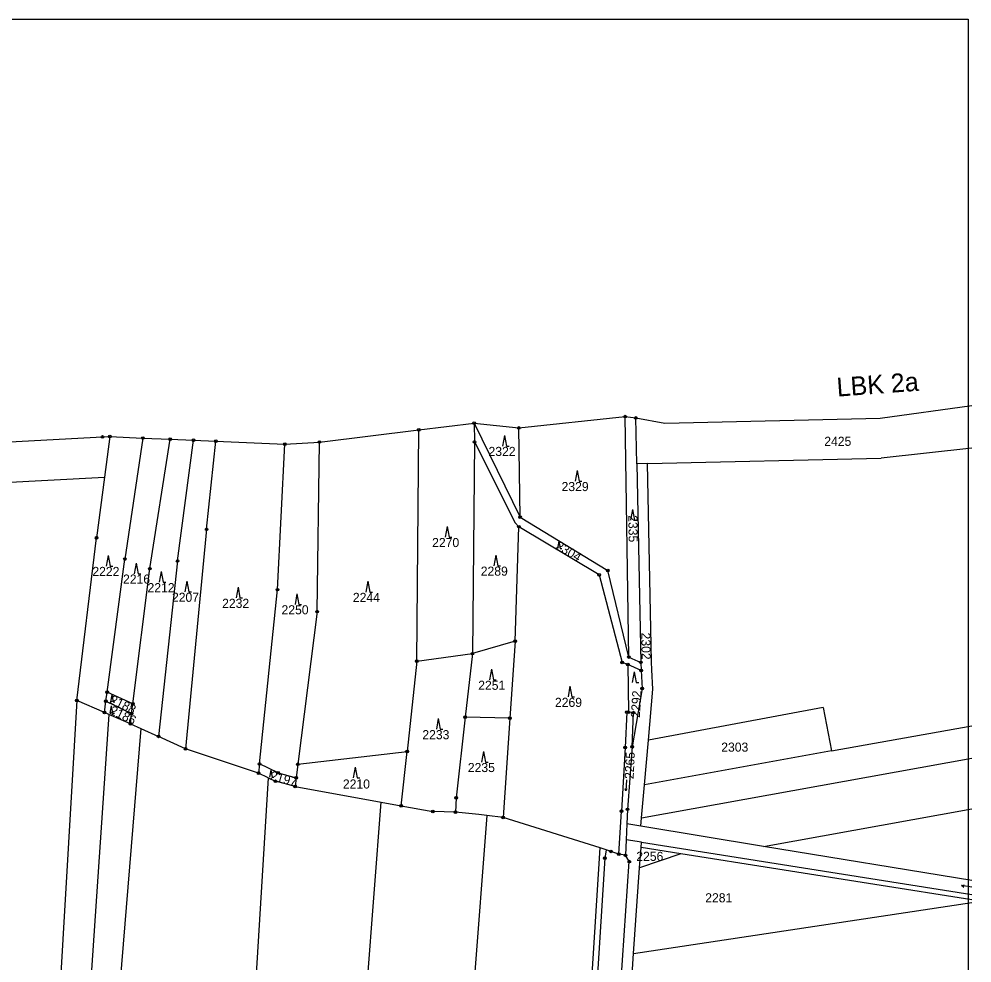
# Model space of a CAD drawing. Extents: x -566461 to -565197, y -1096302 to -1095706.
# Drawn here: x -565553.3 to -565197, y -1096059.8 to -1095707 of the extents above; entities that cross this region are included whole.
import ezdxf

# ---------------------------------------------------------------- set-up
doc = ezdxf.new("R2010")
doc.units = 0
for name, color, linetype in [('Vrstva 1', 7, 'Continuous'), ('Vrstva 13', 7, 'Continuous'), ('Vrstva 18', 7, 'Continuous'), ('Vrstva 24', 7, 'Continuous'), ('Vrstva 25', 7, 'Continuous'), ('Vrstva 63', 7, 'Continuous')]:
    doc.layers.add(name, color=color, linetype=linetype)

msp = doc.modelspace()

# ---------------------------------------------------------------- linework, layer by layer
at = {"layer": 'Vrstva 1'}
for p, q in [((-565325.3, -1095945.49), (-565326.62, -1095855.64)), ((-565322.28, -1095873.28), (-565322.62, -1095856.13)), ((-565404.57, -1095947.01), (-565403.8, -1095860.58)), ((-565383.09, -1095858.05), (-565383.02, -1095865.11)), ((-565383.09, -1095858.05), (-565365.95, -1095893.19)), ((-565365.95, -1095893.19), (-565366.41, -1095859.87)), ((-565519.36, -1095863.08), (-565521.32, -1095878.21)), ((-565506.96, -1095863.62), (-565513.66, -1095908.86)), ((-565504.35, -1095912.44), (-565496.71, -1095864.05)), ((-565493.97, -1095909.58), (-565488.06, -1095864.42)), ((-565483.13, -1095897.74), (-565479.68, -1095864.78)), ((-565456.67, -1095920.29), (-565453.87, -1095865.89)), ((-565441.83, -1095928.52), (-565440.98, -1095865.12)), ((-565383.02, -1095865.11), (-565383.78, -1095944.21)), ((-565383.02, -1095865.11), (-565367.82, -1095895.28)), ((-565196.99, -1095867.39), (-565230.93, -1095871.19)), ((-565318.28, -1095873.19), (-565230.93, -1095871.19)), ((-565318.28, -1095873.19), (-565322.28, -1095873.28)), ((-565322.28, -1095873.28), (-565320.79, -1095947.48)), ((-565316.79, -1095947.33), (-565318.28, -1095873.19)), ((-565568.01, -1095880.69), (-565521.32, -1095878.21)), ((-565521.32, -1095878.21), (-565524.26, -1095900.94)), ((-565366.39, -1095896.77), (-565367.82, -1095895.28)), ((-565365.95, -1095893.19), (-565333.17, -1095913.11)), ((-565483.13, -1095897.74), (-565490.98, -1095979.78)), ((-565367.79, -1095939.56), (-565366.39, -1095896.77)), ((-565336.37, -1095914.75), (-565366.39, -1095896.77)), ((-565531.63, -1095961.73), (-565524.26, -1095900.94)), ((-565520.34, -1095958.64), (-565513.66, -1095908.86)), ((-565493.97, -1095909.58), (-565501.17, -1095975.14)), ((-565510.71, -1095963.01), (-565504.35, -1095912.44)), ((-565325.3, -1095945.49), (-565333.17, -1095913.11)), ((-565336.37, -1095914.75), (-565327.73, -1095947.49)), ((-565463.34, -1095985.45), (-565456.67, -1095920.29)), ((-565441.83, -1095928.52), (-565449.03, -1095985.59)), ((-565367.79, -1095939.56), (-565383.78, -1095944.21)), ((-565367.79, -1095939.56), (-565369.72, -1095968.34)), ((-565404.57, -1095947.01), (-565383.78, -1095944.21)), ((-565383.78, -1095944.21), (-565386.46, -1095967.93)), ((-565325.3, -1095945.49), (-565320.79, -1095947.48)), ((-565404.57, -1095947.01), (-565408.18, -1095980.8)), ((-565325.61, -1095948.29), (-565327.73, -1095947.49)), ((-565325.61, -1095948.29), (-565325.42, -1095966.15)), ((-565320.63, -1095950.54), (-565325.61, -1095948.29)), ((-565320.79, -1095947.48), (-565320.63, -1095950.54)), ((-565316.63, -1095950.33), (-565316.79, -1095947.33)), ((-565320.63, -1095950.54), (-565320.28, -1095957.29)), ((-565316.26, -1095957.53), (-565316.63, -1095950.33)), ((-565520.79, -1095961.97), (-565520.34, -1095958.64)), ((-565510.71, -1095963.01), (-565520.34, -1095958.64)), ((-565320.28, -1095957.29), (-565324.05, -1095979.07)), ((-565317.95, -1095976.6), (-565316.26, -1095957.53)), ((-565531.63, -1095961.73), (-565540.94, -1096119.67)), ((-565521.36, -1095966.2), (-565531.63, -1095961.73)), ((-565521.36, -1095966.2), (-565520.79, -1095961.97)), ((-565520.79, -1095961.97), (-565511.17, -1095966.63)), ((-565511.17, -1095966.63), (-565510.71, -1095963.01)), ((-565519.73, -1095966.91), (-565530.09, -1096119.67)), ((-565519.73, -1095966.91), (-565521.36, -1095966.2)), ((-565511.64, -1095970.44), (-565519.73, -1095966.91)), ((-565511.64, -1095970.44), (-565511.17, -1095966.63)), ((-565326.08, -1095966.11), (-565326.66, -1095979.34)), ((-565326.08, -1095966.11), (-565325.42, -1095966.15)), ((-565323.47, -1095966.28), (-565325.42, -1095966.15)), ((-565324.05, -1095979.07), (-565323.47, -1095966.28)), ((-565252.64, -1095964.38), (-565317.95, -1095976.6)), ((-565252.64, -1095964.38), (-565249.5, -1095980.6)), ((-565511.64, -1095970.44), (-565507.79, -1095972.17)), ((-565386.46, -1095967.93), (-565389.86, -1095998.08)), ((-565369.72, -1095968.34), (-565386.46, -1095967.93)), ((-565369.72, -1095968.34), (-565372.21, -1096005.43)), ((-565249.5, -1095980.6), (-565196.99, -1095971.15)), ((-565507.79, -1095972.17), (-565519.76, -1096119.67)), ((-565507.79, -1095972.17), (-565501.17, -1095975.14)), ((-565490.98, -1095979.78), (-565501.17, -1095975.14)), ((-565319.41, -1095993.25), (-565317.95, -1095976.6)), ((-565463.69, -1095988.88), (-565490.98, -1095979.78)), ((-565449.03, -1095985.59), (-565408.18, -1095980.8)), ((-565410.35, -1096001.11), (-565408.18, -1095980.8)), ((-565326.66, -1095979.34), (-565328.04, -1096003.07)), ((-565324.05, -1095979.07), (-565325.74, -1096002.43)), ((-565249.5, -1095980.6), (-565319.41, -1095993.25)), ((-565463.34, -1095985.45), (-565463.69, -1095988.88)), ((-565456.43, -1095988.79), (-565463.34, -1095985.45)), ((-565449.03, -1095985.59), (-565449.67, -1095990.68)), ((-565320.5, -1096005.65), (-565196.99, -1095983.35)), ((-565460.14, -1095990.61), (-565463.69, -1095988.88)), ((-565456.43, -1095988.79), (-565449.67, -1095990.68)), ((-565460.14, -1095990.61), (-565466.93, -1096101.52)), ((-565460.14, -1095990.61), (-565457.43, -1095991.93)), ((-565450.08, -1095993.9), (-565457.43, -1095991.93)), ((-565449.67, -1095990.68), (-565450.08, -1095993.9)), ((-565450.08, -1095993.9), (-565417.9, -1095999.74)), ((-565320.5, -1096005.65), (-565319.41, -1095993.25)), ((-565427.07, -1096119.67), (-565417.9, -1095999.74)), ((-565417.9, -1095999.74), (-565410.35, -1096001.11)), ((-565389.86, -1095998.08), (-565390.13, -1096003.44)), ((-565410.35, -1096001.11), (-565398.57, -1096003.25)), ((-565390.13, -1096003.44), (-565398.57, -1096003.25)), ((-565329.05, -1096019.13), (-565328.04, -1096003.07)), ((-565325.74, -1096002.43), (-565325.98, -1096007.86)), ((-565274.95, -1096016.25), (-565196.99, -1096002.17)), ((-565381.38, -1096004.3), (-565390.13, -1096003.44)), ((-565378.38, -1096004.67), (-565387.09, -1096119.67)), ((-565378.38, -1096004.67), (-565381.38, -1096004.3)), ((-565372.21, -1096005.43), (-565378.38, -1096004.67)), ((-565336.02, -1096016.85), (-565372.21, -1096005.43)), ((-565320.77, -1096008.72), (-565320.5, -1096005.65)), ((-565325.98, -1096007.86), (-565326.25, -1096013.79)), ((-565320.77, -1096008.72), (-565325.98, -1096007.86)), ((-565274.95, -1096016.25), (-565320.77, -1096008.72)), ((-565326.25, -1096013.79), (-565326.51, -1096019.6)), ((-565320.57, -1096014.69), (-565326.25, -1096013.79)), ((-565342.55, -1096119.67), (-565336.02, -1096016.85)), ((-565333.74, -1096017.57), (-565336.02, -1096016.85)), ((-565333.74, -1096017.57), (-565334.25, -1096020.7)), ((-565332, -1096018.12), (-565333.74, -1096017.57)), ((-565321.24, -1096024.26), (-565320.71, -1096016.69)), ((-565320.71, -1096016.69), (-565320.57, -1096014.69)), ((-565305.78, -1096019.05), (-565320.71, -1096016.69)), ((-565320.57, -1096014.69), (-565196.99, -1096034.23)), ((-565196.99, -1096029.05), (-565274.95, -1096016.25)), ((-565334.25, -1096020.7), (-565340.54, -1096119.67)), ((-565329.05, -1096019.13), (-565332, -1096018.12)), ((-565326.51, -1096019.6), (-565329.05, -1096019.13)), ((-565325.09, -1096021.97), (-565326.51, -1096019.6)), ((-565305.78, -1096019.05), (-565321.24, -1096024.26)), ((-565196.99, -1096036.24), (-565305.78, -1096019.05)), ((-565331.88, -1096119.67), (-565325.09, -1096021.97)), ((-565323.47, -1096056.29), (-565321.24, -1096024.26)), ((-565323.47, -1096056.29), (-565196.99, -1096037.21)), ((-565326.92, -1096105.96), (-565323.47, -1096056.29))]:
    msp.add_line(p, q, dxfattribs=at)
at = {"layer": 'Vrstva 13'}
for p, q in [((-565231.27, -1095856.19), (-565196.99, -1095851.52)), ((-565366.41, -1095859.87), (-565326.62, -1095855.64)), ((-565326.62, -1095855.64), (-565322.62, -1095856.13)), ((-565322.62, -1095856.13), (-565311.82, -1095858.04)), ((-565311.82, -1095858.04), (-565231.27, -1095856.19)), ((-565440.98, -1095865.12), (-565403.8, -1095860.58)), ((-565403.8, -1095860.58), (-565383.09, -1095858.05)), ((-565383.09, -1095858.05), (-565366.41, -1095859.87)), ((-565569.62, -1095865.76), (-565522.03, -1095863.23)), ((-565522.03, -1095863.23), (-565519.36, -1095863.08)), ((-565519.36, -1095863.08), (-565506.96, -1095863.62)), ((-565506.96, -1095863.62), (-565496.71, -1095864.05)), ((-565496.71, -1095864.05), (-565488.06, -1095864.42)), ((-565488.06, -1095864.42), (-565479.68, -1095864.78)), ((-565479.68, -1095864.78), (-565453.87, -1095865.89)), ((-565453.87, -1095865.89), (-565440.98, -1095865.12))]:
    msp.add_line(p, q, dxfattribs=at)
at = {"layer": 'Vrstva 24'}
for centre, radius in [((-565326.62, -1095855.64), 0.5), ((-565326.62, -1095855.64), 0.0327), ((-565322.62, -1095856.13), 0.5), ((-565322.62, -1095856.13), 0.0327), ((-565403.8, -1095860.58), 0.5), ((-565403.8, -1095860.58), 0.0327), ((-565383.09, -1095858.05), 0.5), ((-565383.09, -1095858.05), 0.0327), ((-565366.41, -1095859.87), 0.5), ((-565366.41, -1095859.87), 0.0327), ((-565522.03, -1095863.23), 0.5), ((-565522.03, -1095863.23), 0.0327), ((-565519.36, -1095863.08), 0.5), ((-565519.36, -1095863.08), 0.0327), ((-565506.96, -1095863.62), 0.5), ((-565506.96, -1095863.62), 0.0327), ((-565496.71, -1095864.05), 0.5), ((-565496.71, -1095864.05), 0.0327), ((-565488.06, -1095864.42), 0.5), ((-565488.06, -1095864.42), 0.0327), ((-565479.68, -1095864.78), 0.5), ((-565479.68, -1095864.78), 0.0327), ((-565453.87, -1095865.89), 0.5), ((-565453.87, -1095865.89), 0.0327), ((-565440.98, -1095865.12), 0.5), ((-565440.98, -1095865.12), 0.0327), ((-565383.02, -1095865.11), 0.5), ((-565383.02, -1095865.11), 0.0327), ((-565365.95, -1095893.19), 0.5), ((-565366.39, -1095896.77), 0.5), ((-565365.95, -1095893.19), 0.0327), ((-565483.13, -1095897.74), 0.5), ((-565483.13, -1095897.74), 0.0327), ((-565366.39, -1095896.77), 0.0327), ((-565524.26, -1095900.94), 0.5), ((-565524.26, -1095900.94), 0.0327), ((-565513.66, -1095908.86), 0.5), ((-565513.66, -1095908.86), 0.0327), ((-565493.97, -1095909.58), 0.5), ((-565493.97, -1095909.58), 0.0327), ((-565504.35, -1095912.44), 0.5), ((-565504.35, -1095912.44), 0.0327), ((-565336.37, -1095914.75), 0.5), ((-565333.17, -1095913.11), 0.5), ((-565333.17, -1095913.11), 0.0327), ((-565336.37, -1095914.75), 0.0327), ((-565456.67, -1095920.29), 0.5), ((-565456.67, -1095920.29), 0.0327), ((-565441.83, -1095928.52), 0.5), ((-565441.83, -1095928.52), 0.0327), ((-565367.79, -1095939.56), 0.5), ((-565367.79, -1095939.56), 0.0327), ((-565383.78, -1095944.21), 0.5), ((-565383.78, -1095944.21), 0.0327), ((-565325.3, -1095945.49), 0.5), ((-565325.3, -1095945.49), 0.0327), ((-565404.57, -1095947.01), 0.5), ((-565404.57, -1095947.01), 0.0327), ((-565327.73, -1095947.49), 0.5), ((-565327.73, -1095947.49), 0.0327), ((-565325.61, -1095948.29), 0.5), ((-565325.61, -1095948.29), 0.0327), ((-565320.79, -1095947.48), 0.5), ((-565320.79, -1095947.48), 0.0327), ((-565320.63, -1095950.54), 0.5), ((-565320.63, -1095950.54), 0.0327), ((-565320.28, -1095957.29), 0.5), ((-565520.34, -1095958.64), 0.5), ((-565520.34, -1095958.64), 0.0327), ((-565320.28, -1095957.29), 0.0327), ((-565531.63, -1095961.73), 0.5), ((-565531.63, -1095961.73), 0.0327), ((-565520.79, -1095961.97), 0.5), ((-565520.79, -1095961.97), 0.0327), ((-565510.71, -1095963.01), 0.5), ((-565510.71, -1095963.01), 0.0327), ((-565521.36, -1095966.2), 0.5), ((-565521.36, -1095966.2), 0.0327), ((-565511.17, -1095966.63), 0.5), ((-565511.17, -1095966.63), 0.0327), ((-565386.46, -1095967.93), 0.5), ((-565326.08, -1095966.11), 0.5), ((-565326.08, -1095966.11), 0.0327), ((-565325.42, -1095966.15), 0.5), ((-565325.42, -1095966.15), 0.0327), ((-565323.47, -1095966.28), 0.5), ((-565323.47, -1095966.28), 0.0327), ((-565511.64, -1095970.44), 0.5), ((-565511.64, -1095970.44), 0.0327), ((-565386.46, -1095967.93), 0.0327), ((-565369.72, -1095968.34), 0.5), ((-565369.72, -1095968.34), 0.0327), ((-565501.17, -1095975.14), 0.5), ((-565501.17, -1095975.14), 0.0327), ((-565490.98, -1095979.78), 0.5), ((-565490.98, -1095979.78), 0.0327), ((-565408.18, -1095980.8), 0.5), ((-565408.18, -1095980.8), 0.0327), ((-565326.66, -1095979.34), 0.5), ((-565326.66, -1095979.34), 0.0327), ((-565324.05, -1095979.07), 0.5), ((-565324.05, -1095979.07), 0.0327), ((-565463.34, -1095985.45), 0.5), ((-565463.34, -1095985.45), 0.0327), ((-565449.03, -1095985.59), 0.5), ((-565449.03, -1095985.59), 0.0327), ((-565463.69, -1095988.88), 0.5), ((-565463.69, -1095988.88), 0.0327), ((-565456.43, -1095988.79), 0.5), ((-565456.43, -1095988.79), 0.0327), ((-565457.43, -1095991.93), 0.5), ((-565457.43, -1095991.93), 0.0327), ((-565449.67, -1095990.68), 0.5), ((-565449.67, -1095990.68), 0.0327), ((-565450.08, -1095993.9), 0.5), ((-565450.08, -1095993.9), 0.0327), ((-565389.86, -1095998.08), 0.5), ((-565389.86, -1095998.08), 0.0327), ((-565410.35, -1096001.11), 0.5), ((-565410.35, -1096001.11), 0.0327), ((-565398.57, -1096003.25), 0.5), ((-565398.57, -1096003.25), 0.0327), ((-565390.13, -1096003.44), 0.5), ((-565390.13, -1096003.44), 0.0327), ((-565328.04, -1096003.07), 0.5), ((-565328.04, -1096003.07), 0.0327), ((-565325.74, -1096002.43), 0.5), ((-565325.74, -1096002.43), 0.0327), ((-565372.21, -1096005.43), 0.5), ((-565372.21, -1096005.43), 0.0327), ((-565332, -1096018.12), 0.5), ((-565334.25, -1096020.7), 0.5), ((-565334.25, -1096020.7), 0.0327), ((-565332, -1096018.12), 0.0327), ((-565329.05, -1096019.13), 0.5), ((-565329.05, -1096019.13), 0.0327), ((-565326.51, -1096019.6), 0.5), ((-565326.51, -1096019.6), 0.0327), ((-565325.09, -1096021.97), 0.5), ((-565325.09, -1096021.97), 0.0327)]:
    msp.add_circle(centre, radius, dxfattribs=at)
at = {"layer": 'Vrstva 25'}
for p, q in [((-565371.79, -1095862.63), (-565372.53, -1095866.63)), ((-565371.79, -1095862.63), (-565371.06, -1095866.63)), ((-565371.06, -1095866.63), (-565370.06, -1095866.63)), ((-565344.62, -1095875.75), (-565345.35, -1095879.75)), ((-565344.62, -1095875.75), (-565343.89, -1095879.75)), ((-565343.89, -1095879.75), (-565342.89, -1095879.75)), ((-565323.9, -1095890.3), (-565324.64, -1095894.3)), ((-565323.9, -1095890.3), (-565323.17, -1095894.3)), ((-565323.17, -1095894.3), (-565322.17, -1095894.3)), ((-565393.23, -1095896.68), (-565393.96, -1095900.68)), ((-565393.23, -1095896.68), (-565392.5, -1095900.68)), ((-565392.5, -1095900.68), (-565391.5, -1095900.68)), ((-565351.45, -1095902.21), (-565351.94, -1095904.89)), ((-565351.45, -1095902.21), (-565350.95, -1095904.89)), ((-565350.95, -1095904.89), (-565350.28, -1095904.89)), ((-565519.94, -1095907.49), (-565520.68, -1095911.49)), ((-565519.94, -1095907.49), (-565519.21, -1095911.49)), ((-565509.47, -1095910.34), (-565510.2, -1095914.34)), ((-565509.47, -1095910.34), (-565508.74, -1095914.34)), ((-565374.96, -1095907.38), (-565375.7, -1095911.38)), ((-565374.96, -1095907.38), (-565374.23, -1095911.38)), ((-565519.21, -1095911.49), (-565518.21, -1095911.49)), ((-565508.74, -1095914.34), (-565507.74, -1095914.34)), ((-565500.16, -1095913.55), (-565500.9, -1095917.55)), ((-565500.16, -1095913.55), (-565499.43, -1095917.55)), ((-565374.23, -1095911.38), (-565373.23, -1095911.38)), ((-565499.43, -1095917.55), (-565498.43, -1095917.55)), ((-565490.5, -1095917.13), (-565491.23, -1095921.13)), ((-565490.5, -1095917.13), (-565489.77, -1095921.13)), ((-565422.83, -1095917.19), (-565423.57, -1095921.19)), ((-565422.83, -1095917.19), (-565422.1, -1095921.19)), ((-565489.77, -1095921.13), (-565488.77, -1095921.13)), ((-565471.4, -1095919.41), (-565472.14, -1095923.41)), ((-565471.4, -1095919.41), (-565470.67, -1095923.41)), ((-565422.1, -1095921.19), (-565421.1, -1095921.19)), ((-565470.67, -1095923.41), (-565469.67, -1095923.41)), ((-565449.36, -1095921.82), (-565450.09, -1095925.82)), ((-565449.36, -1095921.82), (-565448.63, -1095925.82)), ((-565448.63, -1095925.82), (-565447.63, -1095925.82)), ((-565376.57, -1095950.03), (-565377.31, -1095954.03)), ((-565376.57, -1095950.03), (-565375.84, -1095954.03)), ((-565323.27, -1095951), (-565324.01, -1095955)), ((-565323.27, -1095951), (-565322.54, -1095955)), ((-565375.84, -1095954.03), (-565374.84, -1095954.03)), ((-565347.28, -1095956.42), (-565348.02, -1095960.42)), ((-565347.28, -1095956.42), (-565346.55, -1095960.42)), ((-565322.54, -1095955), (-565321.54, -1095955)), ((-565518.62, -1095959.61), (-565519.12, -1095962.29)), ((-565518.62, -1095959.61), (-565518.13, -1095962.29)), ((-565346.55, -1095960.42), (-565345.55, -1095960.42)), ((-565518.78, -1095963.76), (-565519.27, -1095966.44)), ((-565518.78, -1095963.76), (-565518.28, -1095966.44)), ((-565518.13, -1095962.29), (-565517.46, -1095962.29)), ((-565518.28, -1095966.44), (-565517.61, -1095966.44)), ((-565396.51, -1095968.5), (-565397.24, -1095972.5)), ((-565396.51, -1095968.5), (-565395.78, -1095972.5)), ((-565395.78, -1095972.5), (-565394.78, -1095972.5)), ((-565379.58, -1095980.77), (-565380.32, -1095984.77)), ((-565379.58, -1095980.77), (-565378.85, -1095984.77)), ((-565378.85, -1095984.77), (-565377.85, -1095984.77)), ((-565459.18, -1095987.74), (-565459.67, -1095990.42)), ((-565459.18, -1095987.74), (-565458.68, -1095990.42)), ((-565427.58, -1095986.68), (-565428.32, -1095990.68)), ((-565427.58, -1095986.68), (-565426.85, -1095990.68)), ((-565458.68, -1095990.42), (-565458.01, -1095990.42)), ((-565426.85, -1095990.68), (-565425.85, -1095990.68)), ((-565326.2, -1095991.44), (-565326.4, -1095995.46)), ((-565196.99, -1096031.55), (-565200.94, -1096030.92))]:
    msp.add_line(p, q, dxfattribs=at)
for points in [[(-565326.03, -1095994.8), (-565326.4, -1095995.46), (-565326.7, -1095994.77)], [(-565200.03, -1096031.57), (-565200.94, -1096030.92), (-565199.88, -1096030.58)]]:
    msp.add_lwpolyline(points, dxfattribs=at)
at = {"layer": 'Vrstva 63'}
for p, q in [((-566458.38, -1095707.03), (-565198.38, -1095707.03)), ((-565198.38, -1095707.03), (-565198.38, -1096301.03))]:
    msp.add_line(p, q, dxfattribs=at)

# ---------------------------------------------------------------- texts
at = {"layer": 'Vrstva 1'}
msp.add_text('LBK 2a', height=7, rotation=4.1596, dxfattribs=at).set_placement((-565247.32, -1095848.16))
at = {"layer": 'Vrstva 18'}
for s, p in [('2425', (-565252.2, -1095866.55)), ('2322', (-565377.73, -1095870.34)), ('2329', (-565350.42, -1095883.46)), ('2270', (-565398.82, -1095904.39)), ('2222', (-565525.86, -1095915.2)), ('2289', (-565380.64, -1095915.09)), ('2216', (-565514.4, -1095918.05)), ('2212', (-565505.23, -1095921.26)), ('2207', (-565496.09, -1095924.84)), ('2244', (-565428.45, -1095924.9)), ('2232', (-565477.34, -1095927.12)), ('2250', (-565455.13, -1095929.53)), ('2251', (-565381.59, -1095957.74)), ('2269', (-565352.9, -1095964.13)), ('2233', (-565402.48, -1095976.21)), ('2303', (-565290.72, -1095980.87)), ('2235', (-565385.47, -1095988.48)), ('2210', (-565432.18, -1095994.64)), ('2256', (-565322.49, -1096021.69)), ('2281', (-565296.71, -1096037.18))]:
    msp.add_text(s, height=3.4, dxfattribs=at).set_placement(p)
for s, rotation, p in [('2335', 270.9, (-565325.48, -1095892.49)), ('2304', 329.4, (-565353.01, -1095904.85)), ('2302', 270.9, (-565320.63, -1095936.38)), ('2188', 333.9, (-565519.71, -1095962.56)), ('2292', 86.4, (-565321.18, -1095968.24)), ('2186', 333.9, (-565519.64, -1095966.53)), ('2265', 87.3, (-565323.49, -1095991.15)), ('2197', 343.8, (-565459.68, -1095991.25))]:
    msp.add_text(s, height=3.4, rotation=rotation, dxfattribs=at).set_placement(p)

doc.saveas('drawing.dxf')
